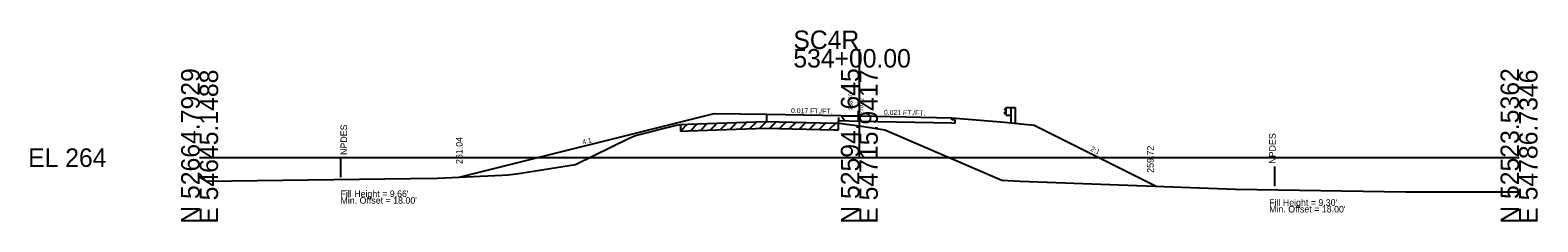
# Model space of a CAD drawing. Extents: x 7498 to 13027, y 90095 to 109625.
# Drawn here: x 9498.3 to 9726.8, y 104095.5 to 104124.4 of the extents above; entities that cross this region are included whole.
import ezdxf

# ---------------------------------------------------------------- set-up
doc = ezdxf.new("R2010")
doc.units = 0
for name, color, linetype in [('Level 10', 7, 'Continuous'), ('Level 11', 7, 'Continuous'), ('Level 12', 7, 'Continuous'), ('Level 24', 7, 'Continuous'), ('Level 32', 7, 'Continuous'), ('Level 33', 7, 'Continuous'), ('Level 50', 7, 'Continuous'), ('Level 53', 7, 'Continuous'), ('Level 55', 7, 'Continuous'), ('Level 59', 7, 'Continuous'), ('Level 6', 7, 'Continuous'), ('Level 60', 7, 'Continuous'), ('Level 61', 7, 'Continuous'), ('Level 63', 7, 'Continuous'), ('Level 7', 7, 'Continuous')]:
    doc.layers.add(name, color=color, linetype=linetype)

msp = doc.modelspace()

# ---------------------------------------------------------------- linework, layer by layer
at = {"layer": 'Level 11'}
for p, q in [((9609.99, 104110.63), (9609.99, 104111.72)), ((9637.99, 104110.89), (9637.99, 104111.19)), ((9638.49, 104110.88), (9637.99, 104110.89)), ((9637.99, 104110.41), (9638.49, 104110.4)), ((9638.49, 104110.4), (9638.49, 104110.88))]:
    msp.add_line(p, q, dxfattribs=at)
at = {"layer": 'Level 12'}
for p, q in [((9620.85, 104110.37), (9620.85, 104110.76)), ((9620.85, 104110.76), (9623.99, 104110.7)), ((9623.99, 104110.7), (9637.99, 104110.41))]:
    msp.add_line(p, q, dxfattribs=at)
at = {"layer": 'Level 24'}
for p, q in [((9646.26, 104112.7), (9645.99, 104112.5)), ((9645.99, 104112.5), (9645.99, 104112.45)), ((9645.99, 104112.45), (9646.26, 104112.25)), ((9645.99, 104111.93), (9646.26, 104112.13)), ((9646.26, 104111.61), (9646.26, 104112.77)), ((9646.26, 104112.77), (9646.93, 104112.77)), ((9646.93, 104112.77), (9646.93, 104110.43)), ((9646.93, 104112.77), (9647.6, 104112.77)), ((9647.6, 104112.77), (9647.6, 104110.36)), ((9645.99, 104111.88), (9645.99, 104111.93)), ((9646.26, 104111.68), (9645.99, 104111.88)), ((9646.26, 104111.61), (9646.93, 104111.61))]:
    msp.add_line(p, q, dxfattribs=at)
at = {"layer": 'Level 53'}
msp.add_line((9620.85, 104111.24), (9620.85, 104110.37), dxfattribs=at)
at = {"layer": 'Level 55'}
for p, q in [((9545.34, 104105.2), (9545.34, 104102.2)), ((9686.96, 104100.84), (9686.96, 104103.84))]:
    msp.add_line(p, q, dxfattribs=at)
at = {"layer": 'Level 59'}
for p, q in [((9609.99, 104111.72), (9623.99, 104111.48)), ((9623.99, 104111.48), (9637.99, 104111.19))]:
    msp.add_line(p, q, dxfattribs=at)
at = {"layer": 'Level 6'}
for p, q in [((9601.99, 104111.86), (9609.99, 104111.72)), ((9637.99, 104111.19), (9645.99, 104110.52)), ((9645.99, 104110.52), (9650.49, 104110.07))]:
    msp.add_line(p, q, dxfattribs=at)
at = {"layer": 'Level 60'}
for p, q in [((9590.07, 104108.53), (9596.29, 104110.09)), ((9596.29, 104110.09), (9596.87, 104110.18)), ((9596.87, 104110.18), (9598.02, 104110.22)), ((9598.02, 104110.22), (9609.69, 104110.64)), ((9609.69, 104110.64), (9620.14, 104110.39)), ((9620.14, 104110.39), (9621, 104110.37)), ((9621, 104110.37), (9621.66, 104110.3)), ((9621.66, 104110.3), (9623.99, 104109.95)), ((9623.99, 104109.95), (9627.85, 104109.38)), ((9580.95, 104104.14), (9589.1, 104108.11)), ((9589.1, 104108.11), (9590.07, 104108.53)), ((9627.85, 104109.38), (9628.9, 104108.92)), ((9628.9, 104108.92), (9645.6, 104101.78)), ((9572, 104102.71), (9580.95, 104104.14)), ((9523.99, 104102.7), (9524.98, 104101.61)), ((9524.98, 104101.61), (9555.94, 104102.03)), ((9555.94, 104102.03), (9560.03, 104102.05)), ((9560.03, 104102.05), (9569.86, 104102.49)), ((9569.86, 104102.49), (9570.72, 104102.56)), ((9570.72, 104102.56), (9572, 104102.71)), ((9645.6, 104101.78), (9648.38, 104101.61)), ((9648.38, 104101.61), (9681.02, 104100.39)), ((9681.02, 104100.39), (9706.81, 104100)), ((9706.81, 104100), (9708.38, 104099.99)), ((9708.38, 104099.99), (9723.99, 104099.99))]:
    msp.add_line(p, q, dxfattribs=at)
at = {"layer": 'Level 61'}
for p, q in [((9597.91, 104110.21), (9596.88, 104109.18)), ((9596.88, 104110.18), (9596.88, 104109.18)), ((9599.42, 104110.27), (9598.38, 104109.23)), ((9600.93, 104110.32), (9599.89, 104109.28)), ((9602.43, 104110.37), (9601.39, 104109.34)), ((9603.93, 104110.43), (9602.89, 104109.39)), ((9605.43, 104110.48), (9604.39, 104109.45)), ((9606.94, 104110.54), (9605.9, 104109.5)), ((9608.44, 104110.59), (9607.4, 104109.55)), ((9609.93, 104110.63), (9608.9, 104109.61)), ((9611.38, 104110.59), (9610.4, 104109.62)), ((9612.89, 104110.56), (9611.91, 104109.58)), ((9614.39, 104110.52), (9613.41, 104109.55)), ((9615.89, 104110.49), (9614.91, 104109.51)), ((9617.39, 104110.45), (9616.41, 104109.47)), ((9618.9, 104110.42), (9617.92, 104109.44)), ((9620.4, 104110.38), (9619.42, 104109.4)), ((9620.85, 104109.37), (9620.85, 104110.37)), ((9596.88, 104109.18), (9598.02, 104109.22)), ((9598.02, 104109.22), (9609.69, 104109.64)), ((9609.69, 104109.64), (9620.14, 104109.39)), ((9620.14, 104109.39), (9620.85, 104109.37))]:
    msp.add_line(p, q, dxfattribs=at)
at = {"layer": 'Level 63'}
for p, q in [((9623.99, 104105.16), (9623.99, 104121.59)), ((9523.99, 104105.16), (9623.99, 104105.16)), ((9623.99, 104105.16), (9723.99, 104105.16))]:
    msp.add_line(p, q, dxfattribs=at)
at = {"layer": 'Level 7'}
for p, q in [((9563.34, 104102.2), (9601.99, 104111.86)), ((9650.49, 104110.07), (9668.96, 104100.84))]:
    msp.add_line(p, q, dxfattribs=at)

# ---------------------------------------------------------------- texts
at = {"layer": 'Level 10'}
msp.add_text('268.80', height=0.6, rotation=90, dxfattribs=at).set_placement((9622.95, 104112.37))
at = {"layer": 'Level 32'}
for s, rotation, p in [('0.017 FT./FT.', 359.0092, (9613.63, 104111.91)), ('0.021 FT./FT.', 358.8084, (9627.71, 104111.65)), ('4:1', 14.0362, (9582.09, 104107.14)), ('2:1', 333.435, (9658.93, 104106.25))]:
    msp.add_text(s, height=0.75, rotation=rotation, dxfattribs=at).set_placement(p)
at = {"layer": 'Level 33'}
for s, p in [('261.04', (9563.84, 104104.2)), ('259.72', (9668.6, 104102.87))]:
    msp.add_text(s, height=1, rotation=90, dxfattribs=at).set_placement(p)
at = {"layer": 'Level 50'}
for p in [(9546.34, 104105.2), (9687.1, 104103.87)]:
    msp.add_text(' NPDES', height=1, rotation=90, dxfattribs=at).set_placement(p)
for s, p in [("Fill Height = 9.66' ", (9545.34, 104099.2)), ("Min. Offset = 18.00' ", (9545.34, 104098.2)), ("Fill Height = 9.30' ", (9686.1, 104097.87)), ("Min. Offset = 18.00' ", (9686.1, 104096.87))]:
    msp.add_text(s, height=1, dxfattribs=at).set_placement(p)
at = {"layer": 'Level 59'}
msp.add_text(' 270.32', height=0.6, rotation=90, dxfattribs=at).set_placement((9624.59, 104111.48))
at = {"layer": 'Level 63'}
for s, p in [('SC4R', (9613.99, 104121.59)), ('534+00.00', (9613.99, 104118.79)), ('EL 264', (9498, 104103.76))]:
    msp.add_text(s, height=2.8, dxfattribs=at).set_placement(p)
for s, p in [('N 52664.7929', (9523.99, 104095.16)), ('E 54645.1488', (9526.79, 104095.16)), ('N 52594.1645', (9623.99, 104095.16)), ('E 54715.9417', (9626.79, 104095.16)), ('N 52523.5362', (9723.99, 104095.16)), ('E 54786.7346', (9726.79, 104095.16))]:
    msp.add_text(s, height=2.8, rotation=90, dxfattribs=at).set_placement(p)

doc.saveas('drawing.dxf')
